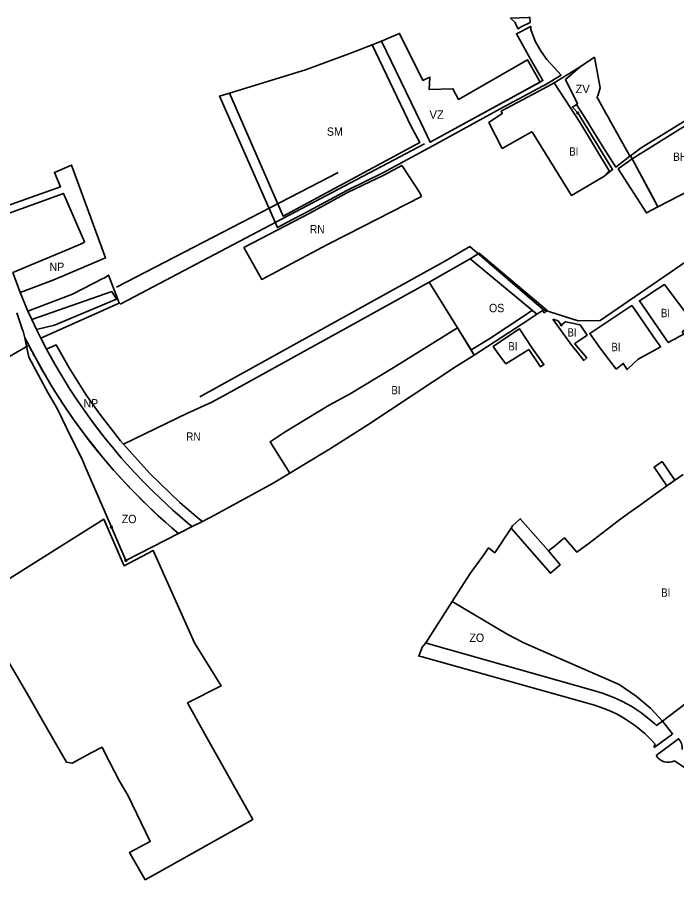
# Model space of a CAD drawing. Extents: x -650276 to -642489, y -1074311 to -1066658.
# Drawn here: x -649019 to -648072, y -1071627 to -1070387 of the extents above; entities that cross this region are included whole.
import ezdxf

# ---------------------------------------------------------------- set-up
doc = ezdxf.new("R2010")
doc.units = 0
doc.header["$LTSCALE"] = 4.8
doc.header["$PDMODE"] = 32
doc.header["$PDSIZE"] = 2.4
for name, color, linetype, lineweight in [('1', 7, 'Continuous', 35), ('15', 7, 'Continuous', 35), ('18', 7, 'Continuous', 35), ('2', 7, 'Continuous', 35), ('24', 7, 'Continuous', 35), ('36', 7, 'Continuous', 35), ('40', 7, 'Continuous', 35), ('42', 7, 'Continuous', 35), ('48', 7, 'Continuous', 35), ('54', 7, 'Continuous', 35), ('7', 7, 'Continuous', 35), ('9', 7, 'Continuous', 35)]:
    doc.layers.add(name, color=color, linetype=linetype, lineweight=lineweight)
doc.layers.add('62', color=7, linetype='Continuous')

msp = doc.modelspace()

# ---------------------------------------------------------------- linework, layer by layer
at = {"layer": '1'}
msp.add_lwpolyline([(-648098.637, -1070659.682), (-648007.838, -1070612.851), (-648019, -1070518), (-648135.47, -1070590.61), (-648105.98, -1070645.91)], close=True, dxfattribs=at)
at = {"layer": '15'}
for p, q in [((-648303.631, -1070834.849), (-648283.19, -1070821.23)), ((-648272.453, -1070814.072), (-648271.1, -1070813.17))]:
    msp.add_line(p, q, dxfattribs=at)
for points in [[(-648303.705, -1070395.035), (-648302.028, -1070398.436), (-648299.32, -1070403.93), (-648295.18, -1070401.23), (-648281.907, -1070394.762), (-648282.582, -1070387.276), (-648284.37, -1070387.85), (-648310.275, -1070388.476)], [(-648550.72, -1070626.869), (-648636.757, -1070673.431), (-648655.178, -1070631.294), (-648714.161, -1070496.376), (-648728.255, -1070500.709), (-648725.835, -1070506.221), (-648668.207, -1070637.453), (-648645.331, -1070689.546), (-648632.652, -1070682.82), (-648599.66, -1070665.32), (-648545.76, -1070636.22), (-648494.04, -1070610.73), (-648417.855, -1070569.57), (-648325.21, -1070518.84), (-648264.56, -1070486.34), (-648260.57, -1070484.2), (-648237.475, -1070470.361), (-648257.96, -1070448.17), (-648266.416, -1070436.404), (-648274.808, -1070421.647), (-648280.974, -1070405.11), (-648281.388, -1070400.523), (-648302.01, -1070411.05), (-648282.01, -1070446.35), (-648263.859, -1070478.393), (-648425.835, -1070567.021), (-648439.409, -1070538.729), (-648495.666, -1070421.476), (-648509.227, -1070426.957), (-648452.97, -1070544.21), (-648440.531, -1070567.236)], [(-648007.838, -1070612.851), (-647999.588, -1070608.596), (-648002, -1070588), (-648010.831, -1070512.588), (-647999.756, -1070505.655), (-647981.81, -1070496.06), (-647950.48, -1070482.79), (-647917.98, -1070472.47), (-647918.54, -1070468.61), (-647918.95, -1070462.36), (-647923.53, -1070462.75), (-647923.247, -1070465.749), (-647953.251, -1070475.276), (-647985.19, -1070488.804), (-647991.539, -1070492.016), (-648005.668, -1070434.145), (-648014.63, -1070439.36), (-648000.442, -1070499.336), (-648019.789, -1070511.293), (-648050.38, -1070530.2), (-648122.57, -1070575), (-648137.78, -1070586.25), (-648135.47, -1070590.61), (-648019, -1070518)], [(-648135.47, -1070590.61), (-648155.582, -1070605.295), (-648115.057, -1070668.651), (-648098.637, -1070659.682)], [(-648092.72, -1071025.89), (-648104.12, -1071033.78), (-648085.73, -1071060.92), (-648074.12, -1071052.75)], [(-648238.84, -1071174.33), (-648256.04, -1071154.5), (-648278.39, -1071128.74), (-648296.34, -1071108.04), (-648307.33, -1071118.47), (-648309.41, -1071121.655), (-648292.587, -1071141.054), (-648270.236, -1071166.815), (-648253.126, -1071186.542)]]:
    msp.add_lwpolyline(points, close=True, dxfattribs=at)
for points in [[(-648213.87, -1070524.8), (-648221.359, -1070516.349), (-648215.48, -1070512.59), (-648214.34, -1070511.86), (-648231.53, -1070476.99), (-648210.48, -1070458.42), (-648247.67, -1070481.57), (-648211, -1070538), (-648168.575, -1070607.847), (-648176.54, -1070616.09)], [(-648176.54, -1070616.09), (-648169.28, -1070610.49), (-648163.8, -1070606.27), (-648213.87, -1070524.8), (-648221.359, -1070516.349), (-648215.48, -1070512.59), (-648214.34, -1070511.86), (-648231.53, -1070476.99), (-648210.48, -1070458.42), (-648247.67, -1070481.57), (-648211, -1070538)], [(-648176.54, -1070616.09), (-648169.28, -1070610.49), (-648163.8, -1070606.27), (-648213.87, -1070524.8)], [(-648211, -1070538), (-648168.575, -1070607.847), (-648176.54, -1070616.09)], [(-648271.1, -1070813.17), (-648267.8, -1070810.96), (-648264.38, -1070808.66), (-648262.15, -1070811.96), (-648257.61, -1070808.91), (-648355.275, -1070726.455), (-648360.83, -1070729.87), (-648366.739, -1070733.501), (-648368.163, -1070734.376), (-648272.453, -1070814.072)], [(-648283.19, -1070821.23), (-648272.45, -1070814.075), (-648278.832, -1070808.761), (-648282.44, -1070810.84), (-648287.74, -1070814.32)], [(-648287.74, -1070814.32), (-648341.58, -1070849.98), (-648366.98, -1070865.44)], [(-648366.98, -1070865.44), (-648362.519, -1070872.788), (-648303.631, -1070834.849)]]:
    msp.add_lwpolyline(points, dxfattribs=at)
msp.add_point((-648213.87, -1070524.8), dxfattribs=at)
at = {"layer": '18'}
msp.add_lwpolyline([(-648636.757, -1070673.431), (-648550.72, -1070626.869), (-648440.531, -1070567.236), (-648452.97, -1070544.21), (-648509.227, -1070426.957), (-648526.28, -1070433.85), (-648538.611, -1070438.388), (-648546.377, -1070441.246), (-648604.92, -1070462.79), (-648714.161, -1070496.376), (-648655.178, -1070631.294)], close=True, dxfattribs=at)
at = {"layer": '2'}
for points in [[(-648247.67, -1070481.57), (-648262.69, -1070489.67), (-648323.59, -1070522.48), (-648322.18, -1070525.44), (-648341.41, -1070538.42), (-648322.16, -1070575.76), (-648289.22, -1070557.15), (-648279.736, -1070551.783), (-648278.89, -1070553.14), (-648222.58, -1070643.48), (-648176.54, -1070616.09), (-648168.575, -1070607.847), (-648211, -1070538)], [(-648114.77, -1070788.08), (-648125.2, -1070794.79), (-648083.65, -1070854.89), (-648076.73, -1070851.07), (-648074.41, -1070849.79), (-648072.59, -1070848.79), (-648065.35, -1070844.8), (-648061.52, -1070842.68), (-648063.76, -1070839.49), (-648056.61, -1070834.26), (-648047.17, -1070827.35), (-648089.27, -1070771.57), (-648104.78, -1070781.65)], [(-648167.6, -1070822.53), (-648196.65, -1070841.7), (-648181.75, -1070862.74), (-648158.58, -1070892.98), (-648148.34, -1070884.92), (-648142.79, -1070893.78), (-648133.14, -1070884.6), (-648127, -1070878.75), (-648122.72, -1070876.44), (-648111.24, -1070870.11), (-648099.85, -1070863.82), (-648094.9, -1070861.09), (-648095.42, -1070860.3), (-648101.45, -1070851.34), (-648132.03, -1070807.05), (-648136.08, -1070801.79), (-648151.77, -1070812.11)], [(-648540.7, -1070928.6), (-648571.14, -1070944.67), (-648634.07, -1070983.17), (-648655.76, -1070997.5), (-648627.39, -1071042.65), (-648605.3, -1071029.34), (-648570.23, -1071008.2), (-648515.46, -1070972.94), (-648389.33, -1070889.79), (-648362.519, -1070872.788), (-648386.587, -1070833.807), (-648479.18, -1070891.26)]]:
    msp.add_lwpolyline(points, close=True, dxfattribs=at)
for points in [[(-648237.46, -1070829.68), (-648241.96, -1070823.46), (-648249.5, -1070821.08)], [(-648249.5, -1070821.08), (-648222.158, -1070859.221), (-648217.1, -1070865.56), (-648205.18, -1070880.5), (-648200.86, -1070877.05)], [(-648210.517, -1070829.445), (-648221.58, -1070827.03), (-648231.22, -1070824.92), (-648237.46, -1070829.68)], [(-648284.02, -1070864.91), (-648267.24, -1070889.9), (-648262.4, -1070886.58), (-648279.39, -1070862.98), (-648297.39, -1070835.36), (-648320.02, -1070850.16), (-648335.19, -1070860.49), (-648326.41, -1070873.55), (-648317.14, -1070885.48)], [(-648218.11, -1070856.44), (-648209.37, -1070850.44), (-648200.17, -1070844.094), (-648210.517, -1070829.445)], [(-648200.86, -1070877.05), (-648212.94, -1070862.74), (-648217.85, -1070856.93), (-648218.11, -1070856.44)], [(-648317.14, -1070885.48), (-648285.72, -1070865.96), (-648284.02, -1070864.91)], [(-648062.53, -1071044.59), (-648085.73, -1071060.92), (-648097.61, -1071069.37), (-648102.55, -1071072.86), (-648125.53, -1071089.51), (-648141.12, -1071100.71), (-648155.77, -1071111.23), (-648172.48, -1071123.95), (-648197.57, -1071143.03), (-648215.08, -1071156.35), (-648232.8, -1071135.6), (-648237.46, -1071139.38), (-648245.49, -1071145.91), (-648256.04, -1071154.5), (-648238.84, -1071174.33), (-648253.126, -1071186.542), (-648292.587, -1071141.054), (-648309.41, -1071121.655), (-648333.002, -1071157.07), (-648341.943, -1071150.071), (-648347.949, -1071158.385), (-648368.48, -1071186.81), (-648394.104, -1071227.17), (-648315.127, -1071274.052), (-648292.406, -1071286.112), (-648274.918, -1071293.751), (-648154.21, -1071346.477), (-648130, -1071363), (-648109, -1071381), (-648091.92, -1071399.07), (-648060.01, -1071374.69)], [(-649055.64, -1071209.682), (-648966.9, -1071154.34), (-648894.684, -1071108.668), (-648867.88, -1071170.58), (-648865.61, -1071175.825), (-648823.531, -1071154.018), (-648764.17, -1071286.65), (-648725.85, -1071348.28), (-648774.371, -1071372.773), (-648749.854, -1071416.727), (-648680.709, -1071540.691), (-648835.095, -1071627.059), (-648857.66, -1071587.83), (-648827.998, -1071572.04), (-648859.97, -1071505.55), (-648872.28, -1071485.58), (-648893.65, -1071443.47), (-648897.169, -1071436.535), (-648912.69, -1071444.48), (-648940.23, -1071459.65), (-648948.27, -1071457.92), (-648976.99, -1071408.03), (-649002.42, -1071363.86), (-649015.83, -1071340.58), (-649031.91, -1071312.65)]]:
    msp.add_lwpolyline(points, dxfattribs=at)
msp.add_point((-648237.46, -1070829.68), dxfattribs=at)
at = {"layer": '24'}
for points in [[(-649019.48, -1070812.18), (-649018.48, -1070815.18), (-649011.24, -1070836.79), (-649010.67, -1070838.5), (-649007.885, -1070848.153), (-648994.464, -1070873.974), (-648982.467, -1070895.704), (-648970.712, -1070915.663), (-648960.268, -1070932.429), (-648949.389, -1070949.031), (-648939.232, -1070963.818), (-648918.601, -1070991.969), (-648896.068, -1071020.184), (-648886.874, -1071031.044), (-648874.793, -1071044.773), (-648863.847, -1071056.723), (-648851.175, -1071069.886), (-648838.696, -1071082.562), (-648823.087, -1071097.562), (-648816.379, -1071103.782), (-648806.239, -1071112.938), (-648797, -1071121), (-648790.23, -1071126.818), (-648787.207, -1071129.363), (-648767.824, -1071119.455), (-648771.725, -1071116.233), (-648781.806, -1071107.721), (-648795.407, -1071095.8), (-648824.292, -1071068.677), (-648839.273, -1071053.556), (-648856.883, -1071034.761), (-648869.629, -1071020.411), (-648880.44, -1071007.703), (-648894.164, -1070990.806), (-648902.714, -1070979.812), (-648912.396, -1070966.893), (-648922.92, -1070952.242), (-648932.78, -1070937.887), (-648943.414, -1070921.659), (-648953.605, -1070905.299), (-648965.093, -1070885.794), (-648976.834, -1070864.527), (-648985.145, -1070848.538), (-648991.386, -1070835.954), (-648998.132, -1070821.723), (-649003.641, -1070809.566), (-649014.888, -1070782.994), (-649025.129, -1070754.377)], [(-648103.894, -1071436.836), (-648079.108, -1071418.564), (-648077.53, -1071417.4), (-648091.92, -1071399.07), (-648100.438, -1071405.517), (-648103.268, -1071402.88), (-648111.646, -1071395.618), (-648123.313, -1071386.696), (-648136.263, -1071378.194), (-648149.571, -1071370.788), (-648162.084, -1071364.918), (-648178.158, -1071358.781), (-648191.25, -1071354.858), (-648426.18, -1071288.32), (-648432.093, -1071286.645), (-648437.16, -1071292.53), (-648442.191, -1071305.453), (-648437.454, -1071306.778), (-648196.236, -1071374.226)], [(-648063.593, -1071439.723), (-648063.862, -1071435.078), (-648064.838, -1071431.28), (-648066.623, -1071427.592), (-648069.022, -1071424.443), (-648101.203, -1071448.31)], [(-648101.203, -1071448.31), (-648098.259, -1071452.196), (-648096.014, -1071454.192), (-648093.059, -1071456.066), (-648089.539, -1071457.489), (-648085.585, -1071458.248), (-648081.642, -1071458.215), (-648078.539, -1071457.636), (-648074.86, -1071456.248)], [(-648074.86, -1071456.248), (-648027.562, -1071487.894)]]:
    msp.add_lwpolyline(points, dxfattribs=at)
for centre, radius, start, end in [((-648244.965, -1071557.871), 190, 41.59858, 75.13936), ((-648083.781, -1071438.172), 20.157, 161.35794, 176.20098)]:
    msp.add_arc(centre, radius, start, end, dxfattribs=at)
at = {"layer": '36'}
msp.add_lwpolyline([(-648495.666, -1070421.476), (-648439.409, -1070538.729), (-648425.835, -1070567.021), (-648267.801, -1070480.55), (-648285.75, -1070448.49), (-648385.085, -1070505.351), (-648393.14, -1070490.07), (-648427.41, -1070491.08), (-648426.05, -1070473.34), (-648436.22, -1070478.01), (-648469.77, -1070410.47), (-648481.18, -1070415.62)], close=True, dxfattribs=at)
at = {"layer": '40'}
msp.add_line((-648214.34, -1070511.86), (-648215.48, -1070512.59), dxfattribs=at)
for points in [[(-648186.441, -1070501.65), (-648186.088, -1070501.313), (-648184.791, -1070500.073), (-648181.386, -1070488.724), (-648189.93, -1070444.71), (-648194.56, -1070447.8), (-648194.56, -1070447.799), (-648209.82, -1070457.98), (-648210.48, -1070458.42), (-648231.53, -1070476.99), (-648214.34, -1070511.86)], [(-648166.63, -1070537.28), (-648170.72, -1070529.92), (-648172.96, -1070525.9), (-648178.7, -1070515.58), (-648184.54, -1070505.07), (-648186.441, -1070501.65)], [(-648215.48, -1070512.59), (-648210.19, -1070521.07), (-648203.83, -1070531.25), (-648197.59, -1070541.27), (-648190.71, -1070552.3), (-648182.98, -1070564.68), (-648171.02, -1070583.86), (-648159.23, -1070602.75), (-648138.93, -1070587.1)], [(-648138.93, -1070587.1), (-648140.05, -1070585.09), (-648166.63, -1070537.28)]]:
    msp.add_lwpolyline(points, dxfattribs=at)
at = {"layer": '42'}
for p, q in [((-648883.73, -1071120.13), (-648862.97, -1071168.09)), ((-648862.97, -1071168.09), (-648787.207, -1071129.363)), ((-648394.104, -1071227.17), (-648432.093, -1071286.645))]:
    msp.add_line(p, q, dxfattribs=at)
for points in [[(-649002.97, -1070857.609), (-649007.885, -1070848.153), (-649003.1, -1070871.35), (-649002.82, -1070872.69), (-649002.62, -1070873.69), (-649002.15, -1070875.96), (-648974.4, -1070927.77), (-648963.5, -1070946.45), (-648959.92, -1070953.73), (-648948.29, -1070977.37), (-648924.92, -1071024.89), (-648922.98, -1071029.49), (-648921.87, -1071032.04), (-648892.82, -1071099.15), (-648883.73, -1071120.13)], [(-648994.42, -1070874.053), (-648994.464, -1070873.974), (-648994.52, -1070873.867)], [(-648982.403, -1070895.812), (-648982.467, -1070895.704), (-648982.524, -1070895.601)], [(-648970.64, -1070915.778), (-648970.712, -1070915.663), (-648970.771, -1070915.564)], [(-648960.194, -1070932.542), (-648960.268, -1070932.429), (-648960.34, -1070932.313)], [(-648949.345, -1070949.096), (-648949.389, -1070949.031), (-648949.428, -1070948.972)], [(-648939.179, -1070963.89), (-648939.232, -1070963.818), (-648939.33, -1070963.675)], [(-648918.464, -1070992.141), (-648918.601, -1070991.969), (-648918.737, -1070991.784)], [(-648292.406, -1071286.112), (-648315.127, -1071274.052), (-648394.104, -1071227.17), (-648432.093, -1071286.645)], [(-648432.093, -1071286.645), (-648426.18, -1071288.32), (-648191.25, -1071354.858)], [(-648091.92, -1071399.07), (-648109, -1071381), (-648130, -1071363), (-648154.21, -1071346.477), (-648274.918, -1071293.751), (-648292.406, -1071286.112)], [(-648191.25, -1071354.858), (-648178.158, -1071358.781), (-648162.084, -1071364.918), (-648149.571, -1071370.788), (-648136.263, -1071378.194), (-648123.313, -1071386.696), (-648111.646, -1071395.618), (-648103.268, -1071402.88), (-648100.438, -1071405.517), (-648091.92, -1071399.07)]]:
    msp.add_lwpolyline(points, dxfattribs=at)
for start, end in [(206.85611, 208.07207), (208.08607, 209.71957), (209.73567, 211.25686), (211.27351, 212.56631), (212.58435, 213.8879), (213.89777, 215.07157), (215.08899, 217.38409), (217.41391, 230.04071)]:
    msp.add_arc((-648232.695, -1070467.567), 863.398, start, end, dxfattribs=at)
for p in [(-648883.73, -1071120.13), (-648862.97, -1071168.09)]:
    msp.add_point(p, dxfattribs=at)
at = {"layer": '48'}
msp.add_line((-648894.164, -1070990.806), (-648880.44, -1071007.703), dxfattribs=at)
for points in [[(-649014.888, -1070782.994), (-648966.35, -1070764.7), (-648908.94, -1070740.19), (-648892.215, -1070733.293), (-648927.2, -1070637.98), (-648941.064, -1070599.735), (-648965.569, -1070610.382), (-648956.687, -1070630.825), (-649050.081, -1070663.981), (-649047.11, -1070674.743), (-648952.455, -1070640.564), (-648922.196, -1070710.207), (-648924.668, -1070712.022), (-648943.837, -1070720.104), (-649025.129, -1070754.377)], [(-648985.145, -1070848.538), (-648872.375, -1070798.112), (-648874.87, -1070791.61), (-648887.84, -1070757.84), (-648894.08, -1070762.22), (-648896.11, -1070762.73), (-648939.5, -1070785.4), (-649003.641, -1070809.566), (-648998.132, -1070821.723), (-648882.919, -1070781.673), (-648876.64, -1070792.6), (-648965.475, -1070829.829), (-648991.386, -1070835.954)]]:
    msp.add_lwpolyline(points, close=True, dxfattribs=at)
for points in [[(-648866.341, -1071000.881), (-648870.479, -1070996.265), (-648900.337, -1070957.964), (-648920.293, -1070929.567), (-648944.376, -1070891.404), (-648963.107, -1070858.328), (-648976.834, -1070864.527)], [(-648976.834, -1070864.527), (-648965.093, -1070885.794), (-648953.605, -1070905.299), (-648943.414, -1070921.659), (-648932.78, -1070937.887), (-648922.92, -1070952.242), (-648912.396, -1070966.893), (-648894.164, -1070990.806)], [(-648880.44, -1071007.703), (-648869.629, -1071020.411), (-648856.883, -1071034.761), (-648839.273, -1071053.556), (-648824.292, -1071068.677), (-648795.407, -1071095.8), (-648777.641, -1071111.238), (-648771.725, -1071116.233), (-648767.824, -1071119.455), (-648752.967, -1071111.861), (-648758.423, -1071107.756), (-648785.386, -1071084.634), (-648828.353, -1071043.265), (-648866.341, -1071000.881)]]:
    msp.add_lwpolyline(points, dxfattribs=at)
at = {"layer": '54'}
for p, q in [((-648876.429, -1070775.252), (-648558.121, -1070610.206)), ((-649003.638, -1070859.543), (-649266.084, -1071012.071))]:
    msp.add_line(p, q, dxfattribs=at)
for points in [[(-648433.898, -1070569.36), (-648868.299, -1070798.03), (-648871.326, -1070799.464)], [(-648756.915, -1070932.76), (-648403.845, -1070737.419), (-648368.964, -1070716.905), (-648263.103, -1070807.79), (-648213.358, -1070823.563), (-648181.392, -1070823.076), (-647966.625, -1070675.686), (-647777.125, -1070608.309)]]:
    msp.add_lwpolyline(points, dxfattribs=at)
at = {"layer": '7'}
for points in [[(-648438.13, -1070644.73), (-648440.8, -1070639.72), (-648465.28, -1070602.24), (-648466.61, -1070600.21), (-648492.47, -1070614.2), (-648544.42, -1070639.42), (-648597.74, -1070668.62), (-648693.45, -1070718.46)], [(-648693.45, -1070718.46), (-648667.72, -1070764.15), (-648574.27, -1070714.5), (-648544.906, -1070699.451), (-648438.13, -1070644.73)]]:
    msp.add_lwpolyline(points, dxfattribs=at)
msp.add_lwpolyline([(-648866.341, -1071000.881), (-648828.353, -1071043.265), (-648785.386, -1071084.634), (-648758.423, -1071107.756), (-648752.967, -1071111.861), (-648734.849, -1071102.599), (-648651.375, -1071057.109), (-648627.39, -1071042.65), (-648655.76, -1070997.5), (-648634.07, -1070983.17), (-648571.14, -1070944.67), (-648540.7, -1070928.6), (-648479.18, -1070891.26), (-648386.587, -1070833.807), (-648427.25, -1070767.95), (-648511.09, -1070814.7), (-648721.54, -1070930.88), (-648740.25, -1070941.21), (-648774.23, -1070956.42)], close=True, dxfattribs=at)
at = {"layer": '9'}
msp.add_lwpolyline([(-648368.163, -1070734.376), (-648427.25, -1070767.95), (-648366.98, -1070865.44), (-648341.58, -1070849.98), (-648287.74, -1070814.32), (-648282.44, -1070810.84), (-648278.832, -1070808.761)], close=True, dxfattribs=at)

# ---------------------------------------------------------------- texts
at = {"layer": '62'}
for s, p in [('ZV', (-648217.069, -1070496.39)), ('VZ', (-648426.778, -1070533.286))]:
    msp.add_text(s, height=12, dxfattribs=at).set_placement(p)
for s, width, p in [('SM', 0.95, (-648574.138, -1070557.646)), ('BI', 0.85, (-648225.838, -1070586.256)), ('BH', 0.9, (-648076.769, -1070593.709)), ('RN', 0.9, (-648598.428, -1070697.883)), ('NP', 0.95, (-648972.583, -1070752.041)), ('OS', 0.95, (-648341.265, -1070811.272)), ('BI', 0.85, (-648094.127, -1070818.398)), ('BI', 0.85, (-648228.397, -1070846.265)), ('BI', 0.85, (-648313.397, -1070866.265)), ('BI', 0.85, (-648165.397, -1070867.265)), ('BI', 0.85, (-648481.397, -1070929.265)), ('NP', 0.95, (-648923.942, -1070948.157)), ('RN', 0.9, (-648776.428, -1070995.883)), ('ZO', 0.95, (-648868.886, -1071114.486)), ('BI', 0.85, (-648093.764, -1071220.263)), ('ZO', 0.95, (-648369.423, -1071285.188))]:
    msp.add_text(s, height=12, dxfattribs=dict(at, width=width)).set_placement(p)

doc.saveas('drawing.dxf')
